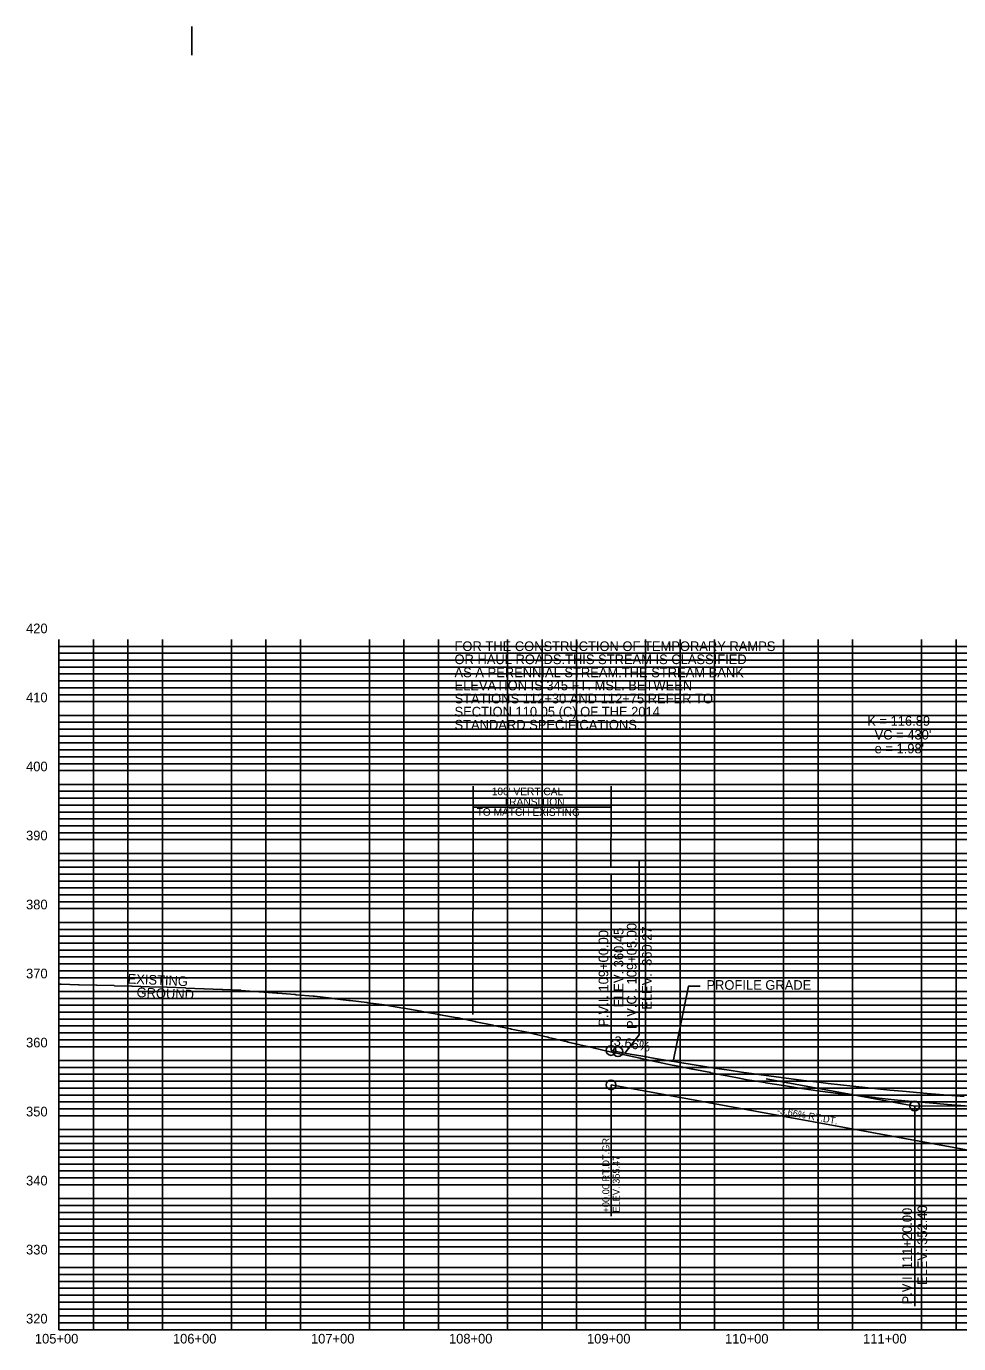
# Model space of a CAD drawing. Extents: x 1627557 to 1636561, y 783843 to 794002.
# Drawn here: x 1635015 to 1635691, y 785820 to 786774 of the extents above; entities that cross this region are included whole.
import ezdxf

# ---------------------------------------------------------------- set-up
doc = ezdxf.new("R2010")
doc.units = 0
for name, color, linetype in [('R_Axis', 7, 'Continuous'), ('R_Axis Annot', 7, 'Continuous'), ('R_Culvert', 7, 'Continuous'), ('R_Exist Surface', 7, 'Continuous'), ('R_Grid', 7, 'Continuous'), ('R_Vert Alg', 7, 'Continuous'), ('R_Vert Alg Annot', 7, 'Continuous'), ('R_Vert Ditch Alg', 7, 'Continuous'), ('R_Vert Ditch Alg Annot', 7, 'Continuous'), ('TEXT', 7, 'Continuous'), ('Transition Dimensions', 7, 'Continuous')]:
    doc.layers.add(name, color=color, linetype=linetype)

msp = doc.modelspace()

# ---------------------------------------------------------------- linework, layer by layer
at = {"layer": 'R_Axis'}
for q in [(1635038.9, 786330.2), (1636538.9, 785830.2)]:
    msp.add_line((1635038.9, 785830.2), q, dxfattribs=at)
at = {"layer": 'R_Culvert'}
msp.add_line((1635135.2, 786753.54), (1635135.2, 786774.32), dxfattribs=at)
at = {"layer": 'R_Exist Surface'}
msp.add_lwpolyline([(1635038.9, 786080.47), (1635039.99, 786080.45), (1635040.53, 786080.43), (1635053, 786080.12), (1635053.5, 786080.11), (1635066.02, 786079.79), (1635066.47, 786079.78), (1635078.86, 786079.42), (1635079.19, 786079.41), (1635091.69, 786079.04), (1635091.92, 786079.03), (1635104.53, 786078.67), (1635104.64, 786078.66), (1635116.97, 786078.3), (1635117.36, 786078.29), (1635117.37, 786078.29), (1635130.67, 786077.73), (1635130.77, 786077.72), (1635143.98, 786077.16), (1635144.17, 786077.16), (1635157.29, 786076.6), (1635157.57, 786076.59), (1635170.59, 786076.04), (1635170.97, 786076.02), (1635183.73, 786075.01), (1635184.22, 786074.97), (1635196.88, 786073.96), (1635197.47, 786073.92), (1635210.03, 786072.92), (1635210.72, 786072.87), (1635223.17, 786071.88), (1635223.98, 786071.82), (1635236.1, 786070.31), (1635236.9, 786070.22), (1635249.01, 786068.71), (1635249.82, 786068.61), (1635261.93, 786067.11), (1635262.74, 786067.01), (1635274.84, 786065.5), (1635275.67, 786065.4), (1635288.01, 786063.19), (1635288.78, 786063.05), (1635301.18, 786060.83), (1635301.9, 786060.7), (1635314.35, 786058.47), (1635315.02, 786058.35), (1635327.52, 786056.11), (1635328.14, 786056), (1635340.41, 786053.44), (1635340.98, 786053.32), (1635353.29, 786050.75), (1635353.82, 786050.64), (1635366.18, 786048.06), (1635366.67, 786047.96), (1635379.06, 786045.37), (1635379.51, 786045.28), (1635393.2, 786042.05), (1635393.68, 786041.94), (1635407.38, 786038.71), (1635407.85, 786038.6), (1635407.91, 786038.58), (1635421.62, 786035.35), (1635422.02, 786035.26), (1635435.87, 786032), (1635436.19, 786031.92), (1635460.05, 786026.84), (1635460.47, 786026.75), (1635484.47, 786021.65), (1635484.76, 786021.58), (1635497.82, 786019.02), (1635497.93, 786019), (1635498.04, 786018.97), (1635511.11, 786016.41), (1635511.18, 786016.39), (1635524.28, 786013.82), (1635524.31, 786013.81), (1635531.66, 786012.37), (1635537.44, 786011.23), (1635537.46, 786011.23), (1635542.62, 786010.42), (1635550.67, 786009.16), (1635550.71, 786009.15), (1635563.89, 786007.09), (1635576.98, 786005.03), (1635577.11, 786005.01), (1635590.15, 786002.97), (1635590.33, 786002.94), (1635603.51, 786001.4), (1635603.73, 786001.38), (1635616.86, 785999.85), (1635617.14, 785999.82), (1635630.22, 785998.29), (1635630.54, 785998.26), (1635630.87, 785998.22), (1635643.94, 785996.7), (1635644.31, 785996.67), (1635656.88, 785995.6), (1635669.54, 785994.53), (1635669.83, 785994.5), (1635682.53, 785993.42), (1635682.77, 785993.4), (1635695.51, 785992.32)], dxfattribs=at)
at = {"layer": 'R_Grid'}
for p, q in [((1635038.9, 786325.2), (1636538.9, 786325.2)), ((1635063.9, 785830.2), (1635063.9, 786330.2)), ((1635088.9, 785830.2), (1635088.9, 786330.2)), ((1635113.9, 785830.2), (1635113.9, 786330.2)), ((1635163.9, 785830.2), (1635163.9, 786330.2)), ((1635188.9, 785830.2), (1635188.9, 786330.2)), ((1635213.9, 785830.2), (1635213.9, 786330.2)), ((1635263.9, 785830.2), (1635263.9, 786330.2)), ((1635288.9, 785830.2), (1635288.9, 786330.2)), ((1635313.9, 785830.2), (1635313.9, 786330.2)), ((1635363.9, 785830.2), (1635363.9, 786330.2)), ((1635388.9, 785830.2), (1635388.9, 786330.2)), ((1635413.9, 785830.2), (1635413.9, 786330.2)), ((1635463.9, 785830.2), (1635463.9, 786330.2)), ((1635488.9, 785830.2), (1635488.9, 786330.2)), ((1635513.9, 785830.2), (1635513.9, 786330.2)), ((1635563.9, 785830.2), (1635563.9, 786330.2)), ((1635588.9, 785830.2), (1635588.9, 786330.2)), ((1635613.9, 785830.2), (1635613.9, 786330.2)), ((1635663.9, 785830.2), (1635663.9, 786330.2)), ((1635688.9, 785830.2), (1635688.9, 786330.2)), ((1635038.9, 786320.2), (1636538.9, 786320.2)), ((1635038.9, 786315.2), (1636538.9, 786315.2)), ((1635038.9, 786310.2), (1636538.9, 786310.2)), ((1635038.9, 786305.2), (1636538.9, 786305.2)), ((1635038.9, 786300.2), (1636538.9, 786300.2)), ((1635038.9, 786295.2), (1636538.9, 786295.2)), ((1635038.9, 786290.2), (1636538.9, 786290.2)), ((1635038.9, 786285.2), (1636538.9, 786285.2)), ((1635038.9, 786275.2), (1636538.9, 786275.2)), ((1635038.9, 786270.2), (1636538.9, 786270.2)), ((1635038.9, 786265.2), (1636538.9, 786265.2)), ((1635038.9, 786260.2), (1636538.9, 786260.2)), ((1635038.9, 786255.2), (1636538.9, 786255.2)), ((1635038.9, 786250.2), (1636538.9, 786250.2)), ((1635038.9, 786245.2), (1636538.9, 786245.2)), ((1635038.9, 786240.2), (1636538.9, 786240.2)), ((1635038.9, 786235.2), (1636538.9, 786235.2)), ((1635038.9, 786225.2), (1636538.9, 786225.2)), ((1635038.9, 786220.2), (1636538.9, 786220.2)), ((1635038.9, 786215.2), (1636538.9, 786215.2)), ((1635038.9, 786210.2), (1636538.9, 786210.2)), ((1635038.9, 786205.2), (1636538.9, 786205.2)), ((1635038.9, 786200.2), (1636538.9, 786200.2)), ((1635038.9, 786195.2), (1636538.9, 786195.2)), ((1635038.9, 786190.2), (1636538.9, 786190.2)), ((1635038.9, 786185.2), (1636538.9, 786185.2)), ((1635038.9, 786175.2), (1636538.9, 786175.2)), ((1635038.9, 786170.2), (1636538.9, 786170.2)), ((1635038.9, 786165.2), (1636538.9, 786165.2)), ((1635038.9, 786160.2), (1636538.9, 786160.2)), ((1635038.9, 786155.2), (1636538.9, 786155.2)), ((1635038.9, 786150.2), (1636538.9, 786150.2)), ((1635038.9, 786145.2), (1636538.9, 786145.2)), ((1635038.9, 786140.2), (1636538.9, 786140.2)), ((1635038.9, 786135.2), (1636538.9, 786135.2)), ((1635038.9, 786125.2), (1636538.9, 786125.2)), ((1635038.9, 786120.2), (1636538.9, 786120.2)), ((1635038.9, 786115.2), (1636538.9, 786115.2)), ((1635038.9, 786110.2), (1636538.9, 786110.2)), ((1635038.9, 786105.2), (1636538.9, 786105.2)), ((1635038.9, 786100.2), (1636538.9, 786100.2)), ((1635038.9, 786095.2), (1636538.9, 786095.2)), ((1635038.9, 786090.2), (1636538.9, 786090.2)), ((1635038.9, 786085.2), (1636538.9, 786085.2)), ((1635038.9, 786075.2), (1636538.9, 786075.2)), ((1635038.9, 786070.2), (1636538.9, 786070.2)), ((1635038.9, 786065.2), (1636538.9, 786065.2)), ((1635038.9, 786060.2), (1636538.9, 786060.2)), ((1635038.9, 786055.2), (1636538.9, 786055.2)), ((1635038.9, 786050.2), (1636538.9, 786050.2)), ((1635038.9, 786045.2), (1636538.9, 786045.2)), ((1635038.9, 786040.2), (1636538.9, 786040.2)), ((1635038.9, 786035.2), (1636538.9, 786035.2)), ((1635038.9, 786025.2), (1636538.9, 786025.2)), ((1635038.9, 786020.2), (1636538.9, 786020.2)), ((1635038.9, 786015.2), (1636538.9, 786015.2)), ((1635038.9, 786010.2), (1636538.9, 786010.2)), ((1635038.9, 786005.2), (1636538.9, 786005.2)), ((1635038.9, 786000.2), (1636538.9, 786000.2)), ((1635038.9, 785995.2), (1636538.9, 785995.2)), ((1635038.9, 785990.2), (1636538.9, 785990.2)), ((1635038.9, 785985.2), (1636538.9, 785985.2)), ((1635038.9, 785975.2), (1636538.9, 785975.2)), ((1635038.9, 785970.2), (1636538.9, 785970.2)), ((1635038.9, 785965.2), (1636538.9, 785965.2)), ((1635038.9, 785960.2), (1636538.9, 785960.2)), ((1635038.9, 785955.2), (1636538.9, 785955.2)), ((1635038.9, 785950.2), (1636538.9, 785950.2)), ((1635038.9, 785945.2), (1636538.9, 785945.2)), ((1635038.9, 785940.2), (1636538.9, 785940.2)), ((1635038.9, 785935.2), (1636538.9, 785935.2)), ((1635038.9, 785925.2), (1636538.9, 785925.2)), ((1635038.9, 785920.2), (1636538.9, 785920.2)), ((1635038.9, 785915.2), (1636538.9, 785915.2)), ((1635038.9, 785910.2), (1636538.9, 785910.2)), ((1635038.9, 785905.2), (1636538.9, 785905.2)), ((1635038.9, 785900.2), (1636538.9, 785900.2)), ((1635038.9, 785895.2), (1636538.9, 785895.2)), ((1635038.9, 785890.2), (1636538.9, 785890.2)), ((1635038.9, 785885.2), (1636538.9, 785885.2)), ((1635038.9, 785875.2), (1636538.9, 785875.2)), ((1635038.9, 785870.2), (1636538.9, 785870.2)), ((1635038.9, 785865.2), (1636538.9, 785865.2)), ((1635038.9, 785860.2), (1636538.9, 785860.2)), ((1635038.9, 785855.2), (1636538.9, 785855.2)), ((1635038.9, 785850.2), (1636538.9, 785850.2)), ((1635038.9, 785845.2), (1636538.9, 785845.2)), ((1635038.9, 785840.2), (1636538.9, 785840.2)), ((1635038.9, 785835.2), (1636538.9, 785835.2))]:
    msp.add_line(p, q, dxfattribs=at)
at = {"layer": 'R_Vert Alg'}
for p, q in [((1635459.35, 786043.85), (1635459.35, 786169.85)), ((1635438.9, 786032.45), (1635438.9, 786160.13)), ((1635438.9, 786032.45), (1635443.9, 786031.54)), ((1635551.4, 786011.87), (1635658.9, 785992.2)), ((1635658.9, 785992.2), (1635766.4, 785992.3)), ((1635658.9, 785992.2), (1635658.9, 785847.14))]:
    msp.add_line(p, q, dxfattribs=at)
msp.add_lwpolyline([(1635443.9, 786031.54), (1635452.86, 786029.91), (1635461.82, 786028.33), (1635470.78, 786026.77), (1635479.73, 786025.25), (1635488.69, 786023.77), (1635497.65, 786022.32), (1635506.61, 786020.9), (1635515.57, 786019.52), (1635524.53, 786018.17), (1635533.48, 786016.86), (1635542.44, 786015.58), (1635551.4, 786014.34), (1635560.36, 786013.13), (1635569.32, 786011.95), (1635578.28, 786010.81), (1635587.23, 786009.71), (1635596.19, 786008.63), (1635605.15, 786007.59), (1635614.11, 786006.59), (1635623.07, 786005.62), (1635632.03, 786004.69), (1635640.98, 786003.79), (1635649.94, 786002.92), (1635667.86, 786001.29), (1635676.82, 786000.52), (1635685.78, 785999.8), (1635694.73, 785999.1)], dxfattribs=at)
for centre in [(1635438.9, 786032.45), (1635443.9, 786031.54), (1635658.9, 785992.2)]:
    msp.add_circle(centre, 3.5, dxfattribs=at)
at = {"layer": 'R_Vert Alg Annot'}
msp.add_line((1635448.9, 786030.62), (1635459.35, 786043.85), dxfattribs=at)
at = {"layer": 'R_Vert Ditch Alg'}
for p, q in [((1635438.9, 786007.55), (1635438.9, 785997.55)), ((1635438.9, 786007.55), (1635738.9, 785952.65)), ((1635438.9, 785997.55), (1635438.9, 785912.55))]:
    msp.add_line(p, q, dxfattribs=at)
msp.add_circle((1635438.9, 786007.55), 3.5, dxfattribs=at)
at = {"layer": 'TEXT'}
msp.add_lwpolyline([(1635503.43, 786079.11), (1635495.11, 786079.11), (1635483.9, 786024.48)], dxfattribs=at)
at = {"layer": 'Transition Dimensions'}
for p, q in [((1635338.94, 786223.97), (1635338.92, 786208.6)), ((1635438.92, 786223.97), (1635438.9, 786208.6)), ((1635338.92, 786208.6), (1635338.77, 786058.54)), ((1635338.92, 786208.6), (1635438.9, 786208.6)), ((1635438.9, 786208.6), (1635438.86, 786164.8))]:
    msp.add_line(p, q, dxfattribs=at)

# ---------------------------------------------------------------- texts
at = {"layer": 'R_Axis Annot'}
for s, p in [('420', (1635015.09, 786334.7)), ('420', (1635015.09, 786334.7)), ('410', (1635015.09, 786284.7)), ('400', (1635015.09, 786234.7)), ('390', (1635015.09, 786184.7)), ('380', (1635015.09, 786134.7)), ('370', (1635015.09, 786084.7)), ('360', (1635015.09, 786034.7)), ('350', (1635015.09, 785984.7)), ('340', (1635015.09, 785934.7)), ('330', (1635015.09, 785884.7)), ('320', (1635015.09, 785834.7)), ('105+00', (1635021.49, 785820.2)), ('106+00', (1635121.5, 785820.2)), ('107+00', (1635221.49, 785820.2)), ('108+00', (1635321.49, 785820.2)), ('109+00', (1635421.49, 785820.2)), ('110+00', (1635521.49, 785820.2)), ('111+00', (1635621.49, 785820.2))]:
    msp.add_text(s, height=7, dxfattribs=at).set_placement(p)
at = {"layer": 'R_Vert Alg Annot'}
for s, p in [('K = 116.89', (1635624.51, 786267.7)), ("VC = 430'", (1635629.85, 786257.7)), ("e = 1.98'", (1635629.85, 786247.7))]:
    msp.add_text(s, height=7, dxfattribs=at).set_placement(p)
for s, rotation, p in [('ELEV. 360.45', 90, (1635447.9, 786063.6)), ('P.V.C . 109+05.00', 90, (1635457.35, 786048.04)), ('ELEV.  360.27', 90, (1635468.35, 786061.96)), ('P.V.I. 109+00.00', 90, (1635436.9, 786049.67)), ('-3.66%', 349.63214, (1635437.46, 786036.83)), ('P.V.I. 111+20.00', 90, (1635656.9, 785848.53)), ('ELEV. 352.40', 90, (1635667.9, 785862.53))]:
    msp.add_text(s, height=7, rotation=rotation, dxfattribs=at).set_placement(p)
at = {"layer": 'R_Vert Ditch Alg Annot'}
for s, rotation, p in [('-3.66% RT.DT.', 349.62962, (1635558.88, 785986.86)), ('+00.00 RT.DT.GR.', 90, (1635437.65, 785915.05)), ('ELEV. 355.47', 90, (1635445.15, 785915.05))]:
    msp.add_text(s, height=5, rotation=rotation, dxfattribs=at).set_placement(p)
at = {"layer": 'TEXT'}
for s, p in [('FOR THE CONSTRUCTION OF TEMPORARY RAMPS', (1635325.5, 786321.81)), ('OR HAUL ROADS.THIS STREAM IS CLASSIFIED', (1635325.5, 786312.33)), ('AS A PERENNIAL STREAM.THE STREAM BANK', (1635325.5, 786302.84)), ('ELEVATION IS 345 FT. MSL. BETWEEN', (1635325.5, 786293.36)), ('STATIONS 112+30 AND 112+75.REFER TO', (1635325.5, 786283.88)), ('SECTION 110.05 (C) OF THE 2014', (1635325.5, 786274.4)), ('STANDARD SPECIFICATIONS.', (1635325.5, 786264.92)), ('PROFILE GRADE', (1635508.02, 786076.42))]:
    msp.add_text(s, height=7, dxfattribs=at).set_placement(p)
for s, p in [('EXISTING', (1635088.55, 786080.97)), ('GROUND', (1635095.02, 786071.18))]:
    msp.add_text(s, height=7, rotation=357.42674, dxfattribs=at).set_placement(p)
at = {"layer": 'Transition Dimensions'}
for s, p in [("100' VERTICAL", (1635352.47, 786217.39)), ('TO MATCH EXISTING', (1635341.52, 786202.51)), ('TRANSITION', (1635360.66, 786209.92))]:
    msp.add_text(s, height=5.5, rotation=359.88664, dxfattribs=at).set_placement(p)

doc.saveas('drawing.dxf')
